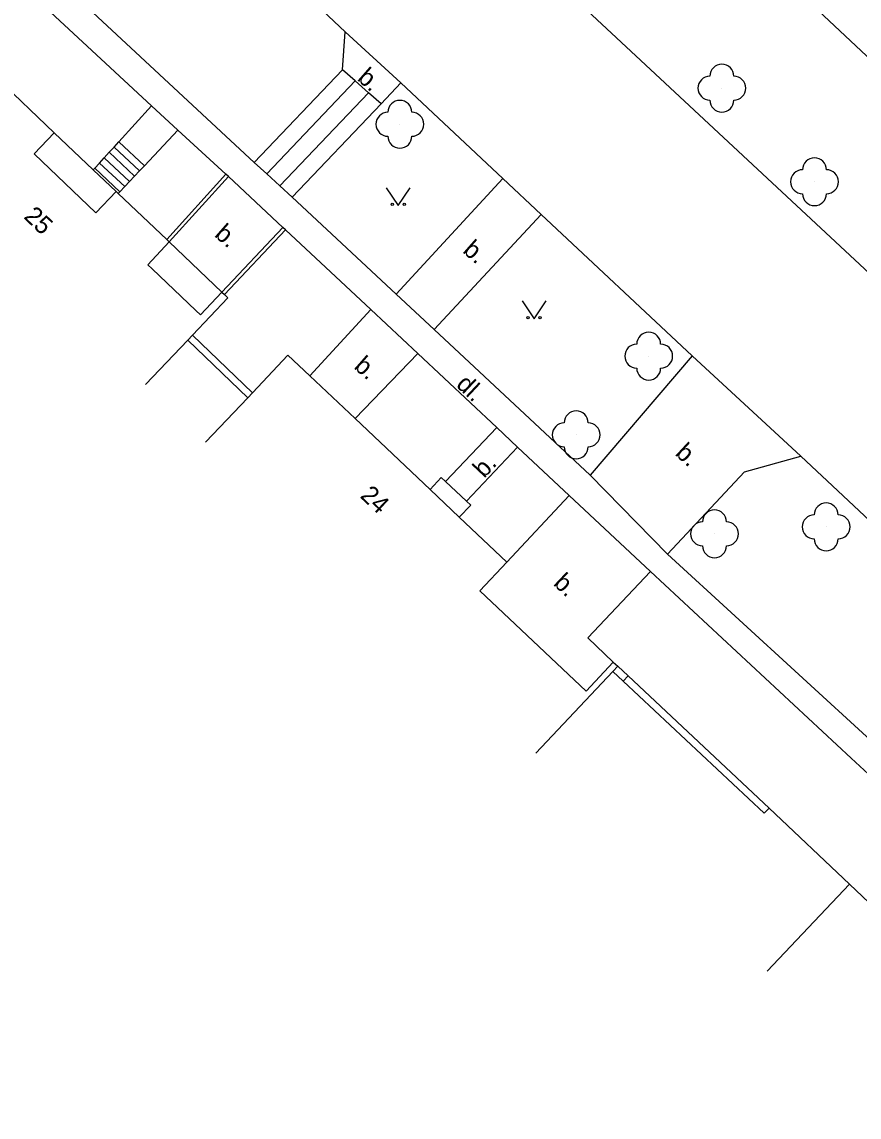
# Model space of a CAD drawing. Extents: x -577457 to -568404, y -1208466 to -1201387.
# Drawn here: x -572983.9 to -572948.91, y -1203330.9 to -1203285.12 of the extents above; entities that cross this region are included whole.
import ezdxf

# ---------------------------------------------------------------- set-up
doc = ezdxf.new("R2010")
doc.units = 0
for name, color, linetype in [('BUDOVY_MĚŘ', 7, 'Continuous'), ('POMOC_POPIS', 7, 'Continuous'), ('ROZHRANÍ_PLOCH', 7, 'Continuous'), ('ZELEŇ', 7, 'Continuous'), ('ZN_DOPLŇKOVÉ', 7, 'Continuous'), ('ZN_KULTUR', 7, 'Continuous'), ('Č_POPIS_ORIENT', 7, 'Continuous')]:
    doc.layers.add(name, color=color, linetype=linetype)

msp = doc.modelspace()

# ---------------------------------------------------------------- linework, layer by layer
at = {"layer": 'BUDOVY_MĚŘ'}
for points in [[(-572984.95, -1203287.47), (-572982.55, -1203289.76)], [(-572982.55, -1203289.76), (-572983.39, -1203290.64), (-572980.81, -1203293.1), (-572979.96, -1203292.21)], [(-572982.55, -1203289.76), (-572980.92, -1203291.3)], [(-572980.92, -1203291.3), (-572979.96, -1203292.21)], [(-572979.96, -1203292.21), (-572979.88, -1203292.29)], [(-572979.88, -1203292.29), (-572977.85, -1203294.22)], [(-572978.46, -1203295.44), (-572978.64, -1203295.27), (-572977.74, -1203294.32)], [(-572977.85, -1203294.22), (-572977.74, -1203294.32)], [(-572977.74, -1203294.32), (-572975.54, -1203296.42)], [(-572975.43, -1203296.52), (-572975.29, -1203296.66), (-572976.77, -1203298.21)], [(-572976.63, -1203297.18), (-572976.44, -1203297.36), (-572975.54, -1203296.42)], [(-572975.54, -1203296.42), (-572975.43, -1203296.52)], [(-572976.97, -1203298.43), (-572978.74, -1203300.28)], [(-572976.77, -1203298.21), (-572976.97, -1203298.43)], [(-572974.26, -1203300.62), (-572972.79, -1203299.05), (-572971.86, -1203299.92)], [(-572971.86, -1203299.92), (-572969.97, -1203301.7)], [(-572974.46, -1203300.84), (-572974.26, -1203300.62)], [(-572976.22, -1203302.69), (-572974.46, -1203300.84)], [(-572969.97, -1203301.7), (-572966.84, -1203304.67)], [(-572966.84, -1203304.67), (-572965.62, -1203305.82)], [(-572965.62, -1203305.82), (-572963.63, -1203307.7)], [(-572963.63, -1203307.7), (-572964.76, -1203308.9), (-572960.32, -1203313.09), (-572959.18, -1203311.88)], [(-572958.99, -1203312.05), (-572959.2, -1203312.27)], [(-572959.18, -1203311.88), (-572958.99, -1203312.05)], [(-572959.2, -1203312.27), (-572962.42, -1203315.69)], [(-572952.75, -1203324.8), (-572949.31, -1203321.17)], [(-572949.31, -1203321.17), (-572942.25, -1203327.85)]]:
    msp.add_lwpolyline(points, dxfattribs=at)
at = {"layer": 'ROZHRANÍ_PLOCH'}
for points in [[(-572996.91, -1203250.52), (-572992.33, -1203245.82), (-572978.62, -1203258.44), (-572957.99, -1203277.72), (-572943.9, -1203290.94), (-572948.47, -1203295.64)], [(-572996.91, -1203250.52), (-572948.47, -1203295.64)], [(-572978.48, -1203288.63), (-572997.29, -1203271.18)], [(-572985.5, -1203271.33), (-572970.39, -1203285.54)], [(-572990.07, -1203276.24), (-572974.19, -1203291)], [(-572970.5, -1203287.13), (-572970.39, -1203285.54)], [(-572970.39, -1203285.54), (-572968.06, -1203287.66)], [(-572974.19, -1203291), (-572970.5, -1203287.13)], [(-572969.97, -1203287.59), (-572970.5, -1203287.13)], [(-572973.67, -1203291.47), (-572969.97, -1203287.59)], [(-572969.42, -1203288.08), (-572969.97, -1203287.59)], [(-572968.06, -1203287.66), (-572968.89, -1203288.54)], [(-572968.06, -1203287.66), (-572963.8, -1203291.67)], [(-572969.42, -1203288.08), (-572973.12, -1203291.97)], [(-572968.89, -1203288.54), (-572969.42, -1203288.08)], [(-572979.85, -1203290.13), (-572978.48, -1203288.63)], [(-572977.39, -1203289.65), (-572978.48, -1203288.63)], [(-572968.89, -1203288.54), (-572972.61, -1203292.45)], [(-572977.39, -1203289.65), (-572978.78, -1203291.13)], [(-572975.38, -1203291.48), (-572977.39, -1203289.65)], [(-572980.05, -1203290.35), (-572979.85, -1203290.13)], [(-572979.85, -1203290.13), (-572978.78, -1203291.13)], [(-572980.46, -1203290.8), (-572980.25, -1203290.57)], [(-572980.25, -1203290.57), (-572980.05, -1203290.35)], [(-572980.25, -1203290.57), (-572979.19, -1203291.57)], [(-572980.05, -1203290.35), (-572978.99, -1203291.35)], [(-572980.86, -1203291.24), (-572980.66, -1203291.02)], [(-572980.66, -1203291.02), (-572980.46, -1203290.8)], [(-572980.66, -1203291.02), (-572979.6, -1203292)], [(-572980.46, -1203290.8), (-572979.4, -1203291.79)], [(-572978.78, -1203291.13), (-572978.99, -1203291.35)], [(-572974.19, -1203291), (-572973.67, -1203291.47)], [(-572980.92, -1203291.3), (-572980.86, -1203291.24)], [(-572980.86, -1203291.24), (-572979.81, -1203292.22)], [(-572979.19, -1203291.57), (-572979.4, -1203291.79)], [(-572978.99, -1203291.35), (-572979.19, -1203291.57)], [(-572975.27, -1203291.58), (-572975.38, -1203291.48)], [(-572972.99, -1203293.71), (-572975.27, -1203291.58)], [(-572973.67, -1203291.47), (-572973.12, -1203291.97)], [(-572979.6, -1203292), (-572979.81, -1203292.22)], [(-572979.4, -1203291.79), (-572979.6, -1203292)], [(-572973.12, -1203291.97), (-572972.61, -1203292.45)], [(-572968.26, -1203296.5), (-572963.8, -1203291.67)], [(-572963.8, -1203291.67), (-572962.19, -1203293.17)], [(-572979.81, -1203292.22), (-572979.88, -1203292.29)], [(-572972.61, -1203292.45), (-572968.26, -1203296.5)], [(-572966.67, -1203297.98), (-572962.19, -1203293.17)], [(-572962.19, -1203293.17), (-572955.88, -1203299.08)], [(-572972.88, -1203293.81), (-572972.99, -1203293.71)], [(-572969.32, -1203297.14), (-572972.88, -1203293.81)], [(-572968.26, -1203296.5), (-572966.67, -1203297.98)], [(-572971.86, -1203299.92), (-572969.32, -1203297.14)], [(-572967.35, -1203298.98), (-572969.32, -1203297.14)], [(-572966.67, -1203297.98), (-572960.15, -1203304.06)], [(-572969.97, -1203301.7), (-572967.35, -1203298.98)], [(-572964.05, -1203302.07), (-572967.35, -1203298.98)], [(-572955.88, -1203299.08), (-572960.15, -1203304.06)], [(-572955.88, -1203299.08), (-572951.34, -1203303.27)], [(-572966.19, -1203304.33), (-572964.05, -1203302.07)], [(-572963.18, -1203302.9), (-572964.05, -1203302.07)], [(-572965.31, -1203305.16), (-572963.18, -1203302.9)], [(-572961.03, -1203304.92), (-572963.18, -1203302.9)], [(-572956.92, -1203307.37), (-572953.7, -1203303.93), (-572951.34, -1203303.27)], [(-572951.34, -1203303.27), (-572928.55, -1203324.63)], [(-572966.84, -1203304.67), (-572966.37, -1203304.16), (-572966.19, -1203304.33)], [(-572966.19, -1203304.33), (-572965.31, -1203305.16)], [(-572960.15, -1203304.06), (-572956.92, -1203307.37)], [(-572965.31, -1203305.16), (-572965.14, -1203305.32), (-572965.62, -1203305.82)], [(-572963.63, -1203307.7), (-572961.03, -1203304.92)], [(-572957.63, -1203308.09), (-572961.03, -1203304.92)], [(-572956.92, -1203307.37), (-572948.43, -1203315.15), (-572932.88, -1203329.47)], [(-572957.63, -1203308.09), (-572960.25, -1203310.87), (-572959.18, -1203311.88)], [(-572934.23, -1203330.9), (-572933.66, -1203330.28), (-572949.23, -1203315.89), (-572957.63, -1203308.09)]]:
    msp.add_lwpolyline(points, dxfattribs=at)
at = {"layer": 'ZELEŇ'}
for centre in [(-572954.64, -1203287.89), (-572968.1, -1203289.4), (-572950.77, -1203291.8), (-572957.7, -1203299.09), (-572960.73, -1203302.38), (-572950.28, -1203306.23), (-572954.95, -1203306.52)]:
    msp.add_circle(centre, 0.0005, dxfattribs=at)
for centre, start, end in [((-572954.64, -1203287.39), 0, 180), ((-572955.14, -1203287.89), 90, 270), ((-572954.14, -1203287.89), 270, 90), ((-572968.1, -1203288.9), 0, 180), ((-572954.64, -1203288.39), 180, 360), ((-572968.6, -1203289.4), 90, 270), ((-572967.6, -1203289.4), 270, 90), ((-572968.1, -1203289.9), 180, 360), ((-572950.77, -1203291.3), 0, 180), ((-572951.27, -1203291.8), 90, 270), ((-572950.27, -1203291.8), 270, 90), ((-572950.77, -1203292.3), 180, 360), ((-572957.7, -1203298.59), 0, 180), ((-572958.2, -1203299.09), 90, 270), ((-572957.2, -1203299.09), 270, 90), ((-572957.7, -1203299.59), 180, 360), ((-572960.73, -1203301.88), 0, 180), ((-572961.23, -1203302.38), 90, 270), ((-572960.23, -1203302.38), 270, 90), ((-572960.73, -1203302.88), 180, 360), ((-572950.28, -1203305.73), 0, 180), ((-572954.95, -1203306.02), 0, 180), ((-572950.78, -1203306.23), 90, 270), ((-572949.78, -1203306.23), 270, 90), ((-572955.45, -1203306.52), 90, 270), ((-572954.45, -1203306.52), 270, 90), ((-572954.95, -1203307.02), 180, 360), ((-572950.28, -1203306.73), 180, 360)]:
    msp.add_arc(centre, 0.5, start, end, dxfattribs=at)
at = {"layer": 'ZN_DOPLŇKOVÉ'}
for points in [[(-572975.38, -1203291.48), (-572977.85, -1203294.22)], [(-572977.74, -1203294.32), (-572975.27, -1203291.58)], [(-572975.54, -1203296.42), (-572972.99, -1203293.71)], [(-572975.43, -1203296.52), (-572972.88, -1203293.81)], [(-572976.63, -1203297.18), (-572978.46, -1203295.44)], [(-572976.97, -1203298.43), (-572974.46, -1203300.84)], [(-572976.77, -1203298.21), (-572974.26, -1203300.62)], [(-572958.99, -1203312.05), (-572958.56, -1203312.46)], [(-572959.2, -1203312.27), (-572958.77, -1203312.68)], [(-572958.56, -1203312.46), (-572958.77, -1203312.68)], [(-572958.56, -1203312.46), (-572952.66, -1203317.98)], [(-572952.66, -1203317.98), (-572952.87, -1203318.2), (-572958.77, -1203312.68)], [(-572949.31, -1203321.17), (-572952.66, -1203317.98)]]:
    msp.add_lwpolyline(points, dxfattribs=at)
at = {"layer": 'ZN_KULTUR'}
for points in [[(-572968.67, -1203292.05), (-572968.17, -1203292.8), (-572967.67, -1203292.05)], [(-572962.99, -1203296.78), (-572962.49, -1203297.53), (-572961.99, -1203296.78)]]:
    msp.add_lwpolyline(points, dxfattribs=at)
for centre in [(-572968.42, -1203292.75), (-572967.92, -1203292.75), (-572962.74, -1203297.48), (-572962.24, -1203297.48)]:
    msp.add_circle(centre, 0.05, dxfattribs=at)

# ---------------------------------------------------------------- texts
at = {"layer": 'POMOC_POPIS'}
for s, rotation, p in [('b.', 318.79, (-572969.92, -1203287.53)), ('b.', 318.79, (-572975.89, -1203294.06)), ('b.', 318.79, (-572965.51, -1203294.73)), ('b.', 318.79, (-572970.06, -1203299.58)), ('dl.', 316.88, (-572965.79, -1203300.33)), ('b.', 317.3, (-572956.63, -1203303.2)), ('b.', 46.59, (-572964.58, -1203304.22)), ('b.', 316.63, (-572961.72, -1203308.63))]:
    msp.add_text(s, height=0.75, rotation=rotation, dxfattribs=at).set_placement(p)
at = {"layer": 'Č_POPIS_ORIENT'}
for s, rotation, p in [('25', 316.43, (-572983.86, -1203293.3)), ('24', 316.64, (-572969.8, -1203304.97))]:
    msp.add_text(s, height=0.75, rotation=rotation, dxfattribs=at).set_placement(p)

doc.saveas('drawing.dxf')
